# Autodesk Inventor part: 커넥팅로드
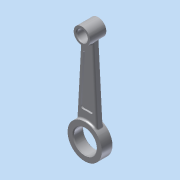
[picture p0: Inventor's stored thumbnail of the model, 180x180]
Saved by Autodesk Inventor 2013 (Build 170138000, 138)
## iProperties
Created: 2016-11
Part Number: 커넥팅로드
Material: 알루미늄 6061
Document SubType Name: Modeling
Designer: mduedu
Density: 1 g/cm^3
Author: mduedu
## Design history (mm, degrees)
sketch "스케치1" dims "d0" = 42, "d3" = 20
  geometry: L1 (0, 0)-(0, 114); L2 (-7.5, 107.386)-(-12.5, 16.875); L3 (7.5, 107.386)-(12.5, 16.875); C1 r 14 at (0, 0); C2 r 6.5 at (0, 114); 3 further points
  constraints: 6 end point, 4 coincident, 2 centre point, 2 symmetric about line, 1 vertical, 6 other
  dimensions: "d1" = 28 diameter of C1; "d2" = 13 diameter of C2; "d4" = 114 distance of L1.start L1.end; "d6" = 12.5 distance from line of L1 L2.end; "d7" = 7.5 distance from line of L1 L2.start
extrude "돌출1" new body sketch "스케치1" stored distance "d8" = 13; taper "d9" = 0 deg
extrude "돌출2" join sketch "스케치1" stored distance "d10" = 20; taper "d11" = 0 deg
sketch "스케치2"
  geometry: L1 (-7.5, 107.386)-(-12.5, 16.875) reference; L2 (7.5, 107.386)-(12.5, 16.875) reference; A1 r 10 centre (0, 114) between (-7.5, 107.386) and (7.5, 107.386) reference; A2 r 21 centre (0, 0) between (-12.5, 16.875) and (12.5, 16.875) reference; 1 further point
extrude "돌출3" join sketch "스케치2" stored distance "d12" = 8; taper "d13" = 0 deg
sketch "스케치3"
  geometry: L1 (-7.5, 107.386)-(-12.5, 16.875) reference; L2 (7.5, 107.386)-(12.5, 16.875) reference; L3 (-4.209, 94.448)-(-7.768, 30.011); L4 (4.209, 94.448)-(7.768, 30.011); L5 (0, 94)-(0, 31); A1 r 10 centre (0, 114) between (-7.5, 107.386) and (7.5, 107.386) reference; A2 r 21 centre (0, 0) between (-12.5, 16.875) and (12.5, 16.875) reference; A3 r 20 centre (0, 114) between (-4.209, 94.448) and (4.209, 94.448); A4 r 31 centre (0, 0) between (7.768, 30.011) and (-7.768, 30.011); 1 further point
  constraints: 6 end point, 6 point on circle, 2 centre point, 2 parallel, 1 symmetric about line, 1 vertical alignment
  dimensions: "d18" = 10 radial gap between concentric circles of A3 A1; "d19" = 10 radial gap between concentric circles of A2 A4; "d20" = 4 distance between parallel lines of L3 L1
extrude "돌출4" cut sketch "스케치3" distance "d21" = 2; taper "d22" = 0 deg
fillet "모깎기1" dims "d23" = 3
fillet "모깎기2" dims "d24" = 2
fillet "모깎기3" dims "d25" = 2
chamfer "모따기1" distance "d26" = 1; stored, may be unused: second distance "d27" = 2, angle "d28" = 45 deg
node "솔리드1"
mirror "대칭1"
other parameters: "d16" = 4, "d17" = 4
